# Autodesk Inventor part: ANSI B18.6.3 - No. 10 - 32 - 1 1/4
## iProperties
Comments: To add or edit properties for Autodesk Inventor files, use iProperties.
Created: 2005-01
Part Number: ANSI B18.6.3 - No. 10 - 32 - 1 1/4
Vendor: Autodesk Inc.
Document SubType Name: Modeling
Designer: John Blackburn
Material: Default
Description: Slotted Pan Head Machine Screw
Standard: ANSI B18.6.3
Alert: To add or edit properties for Autodesk Inventor files, use iProperties.
Control State: 0
Master: False
Checked Out: False
Shininess: 64.0
Length Units: 11272
Angle Units: 11279
Time Units: 11290
Mass Units: 11286
Length Display Precision: 3
Angle Display Precision: 2
Compacted: True
EGR: 4
Classification: un/spsc 31161504
Density: 0.0
Volumn: 0.0
Area: 0.0
PropertySet Name: Model Information
Author: John Blackburn
Revision Number: 9
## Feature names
1. Body [Revolution]
2. Fillet1
3. Slot [Extrusion]
4. Chamfer1
